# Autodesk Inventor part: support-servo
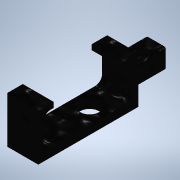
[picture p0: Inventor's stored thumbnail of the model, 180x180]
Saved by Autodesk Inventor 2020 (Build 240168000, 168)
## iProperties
Created: 2023-10
Part Number: support-servo
Material: Générique
Document SubType Name: Modeling
Designer: bruno
Density: 1 g/cm^3
Appearance: Noir
Author: bruno
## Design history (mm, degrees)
sketch "Esquisse1"
  geometry: L1 (0, 0)-(27, 0); L2 (27, -58)-(0, -58); L3 (0, -58)-(0, 0); L4 (20, -3)-(9, -3); L5 (5, -7)-(5, -51); L6 (9, -55)-(20, -55); L7 (24, -49)-(27, -49); L8 (24, -9)-(27, -9); L9 (24, -51)-(24, -49); L10 (24, -9)-(24, -7); L11 (27, 0)-(27, -9); L12 (27, -49)-(27, -58); A1 r 4 centre (20, -7) between (24, -7) and (20, -3); A2 r 4 centre (9, -7) between (9, -3) and (5, -7); A3 r 4 centre (9, -51) between (5, -51) and (9, -55); A4 r 4 centre (20, -51) between (20, -55) and (24, -51)
  constraints: 24 end point, 8 point on circle, 8 tangent, 7 perpendicular, 6 parallel, 4 centre point, 3 equal radius, 2 horizontal
  dimensions: "d0" = 27 distance of L2.start L2.end; "d1" = 58 distance of L1.end L2.start; "d2" = 5 distance between parallel lines of L3 L5; "d3" = 3 distance between parallel lines of L2 L6; "d4" = 3 distance between parallel lines of L1 L4; "d6" = 9 distance between parallel lines of L2 L7; "d7" = 9 distance between parallel lines of L1 L8; "d8" = 4 radius of A1
extrude "Extrusion1" new body sketch "Esquisse1" distance "d9" = 18; taper "d10" = 0 deg
sketch "Esquisse3"
  geometry: L1 (-15, 19)-(-3, 19); L2 (-3, 19)-(-3, 7); L3 (-3, 7)-(-15, 7); L4 (-15, 7)-(-15, 19); L5 (0, 0)-(-18, 0) reference; L6 (-18, 0)-(-18, 27) reference
  constraints: 8 end point, 2 parallel, 1 horizontal, 1 perpendicular
  dimensions: "d11" = 12 distance of L2.end L3.end; "d12" = 12 distance of L1.end L2.end; "d13" = 19 distance between parallel lines of L5 L1; "d14" = 3 distance between parallel lines of L6 L4
extrude "Extrusion2" join sketch "Esquisse3" distance "d15" = 20; taper "d16" = 0 deg
fillet "Congé1" dims "d17" = 2
chamfer "Chanfrein1" distance "d18" = 1; stored, may be unused: second distance "d19" = 2, angle "d20" = 45 deg
sketch "Esquisse4"
  geometry: C1 r 1 at (4.05, -43.823); C2 r 1 at (13.45, -43.823); C3 r 1 at (4.05, 3.823); C4 r 1 at (13.45, 3.823); A1 r 2.2 centre (4.05, -43.823) between (5.102, -45.755) and (2.998, -45.755) reference; A2 r 2.2 centre (13.45, -43.823) between (14.502, -45.755) and (12.398, -45.755) reference; A3 r 2.2 centre (13.45, 3.823) between (12.398, 5.755) and (14.502, 5.755) reference; A4 r 2.2 centre (4.05, 3.823) between (2.998, 5.755) and (5.102, 5.755) reference; 1 further point
  constraints: 4 centre point, 4 coincident
  dimensions: "d21" = 2 diameter of C1; "d22" = 2 diameter of C2; "d23" = 2 diameter of C3; "d24" = 2 diameter of C4
extrude "Extrusion3" cut sketch "Esquisse4" distance "d25" = 10; taper "d26" = 0 deg
sketch "Esquisse6"
  geometry: C1 r 5.5 at (8.782, 18.996); 1 further point
  constraints: 1 centre point
  dimensions: "d29" = 11 diameter of C1
extrude "Extrusion5" cut sketch "Esquisse6" distance "d30" = 10; taper "d31" = 0 deg
node "Solide1"
node "Référence1"
node "Référence2"
node "Référence3"
node "Référence4"
other parameters: "d5" = 3
